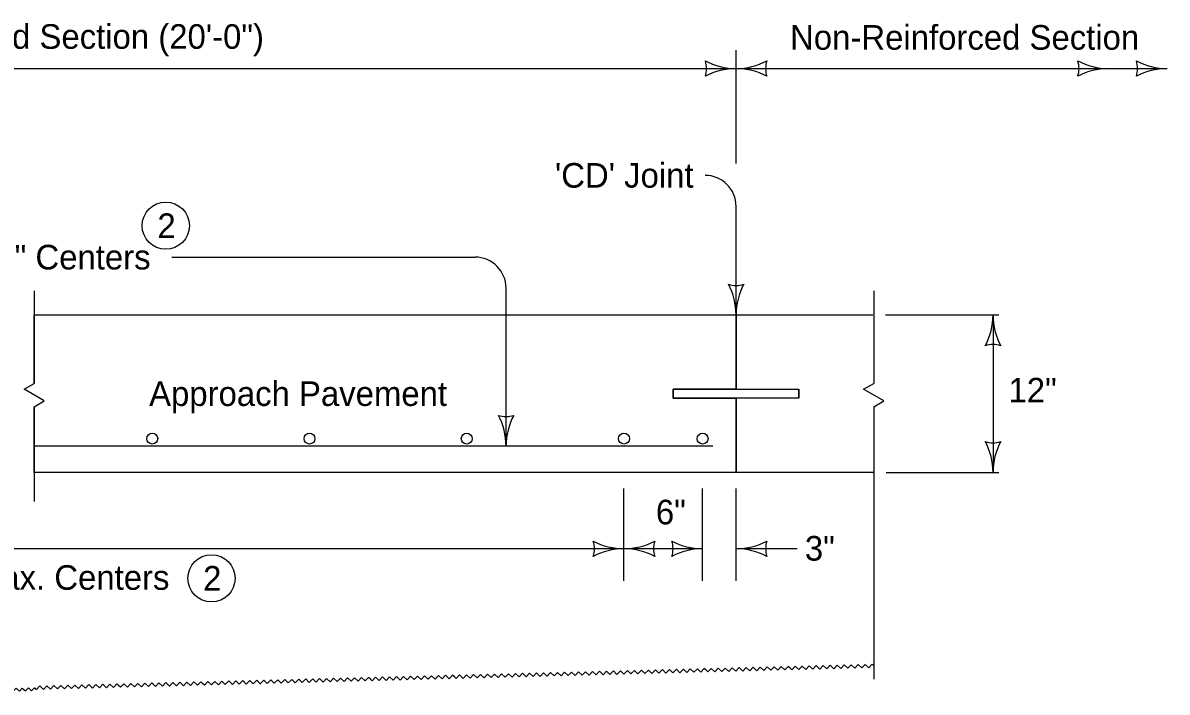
# Model space of a CAD drawing. Extents: x -2134860 to -2124557, y -2139046 to -2137324.
# Drawn here: x -2132638 to -2131894, y -2137759 to -2137324 of the extents above; entities that cross this region are included whole.
import ezdxf

# ---------------------------------------------------------------- set-up
doc = ezdxf.new("R2010")
doc.units = 0
for name, color, linetype in [('BridgeSuperStructureExisting', 7, 'Continuous'), ('dsnCellElements', 7, 'Continuous'), ('dsnStdLabel', 7, 'Continuous')]:
    doc.layers.add(name, color=color, linetype=linetype)

msp = doc.modelspace()

# ---------------------------------------------------------------- linework, layer by layer
at = {"layer": 'BridgeSuperStructureExisting'}
for p, q in [((-2132630.71, -2137498.29), (-2132630.71, -2137558.37)), ((-2132084.45, -2137498.29), (-2132084.45, -2137558.37)), ((-2132173.99, -2137562.24), (-2132173.99, -2137513.93)), ((-2132214.91, -2137567.92), (-2132214.91, -2137562.24)), ((-2132214.91, -2137562.24), (-2132133.06, -2137562.24)), ((-2132133.06, -2137562.24), (-2132133.06, -2137567.92)), ((-2132133.06, -2137567.92), (-2132214.91, -2137567.92)), ((-2132173.99, -2137616.23), (-2132173.99, -2137567.92)), ((-2132630.71, -2137573.53), (-2132630.71, -2137635.08)), ((-2132084.45, -2137573.53), (-2132084.45, -2137750.77)), ((-2132189.05, -2137599.18), (-2132630.71, -2137599.18))]:
    msp.add_line(p, q, dxfattribs=at)
for points in [[(-2132630.7, -2137573.53), (-2132624.14, -2137569.74), (-2132637.28, -2137562.15), (-2132630.7, -2137558.37)], [(-2132084.45, -2137573.53), (-2132077.88, -2137569.74), (-2132091.01, -2137562.15), (-2132084.45, -2137558.37)]]:
    msp.add_lwpolyline(points, dxfattribs=at)
for centre, radius in [((-2132545.06, -2137455.88), 15.36), ((-2132553.84, -2137594.28), 3.55), ((-2132451.53, -2137594.28), 3.55), ((-2132349.23, -2137594.28), 3.55), ((-2132246.92, -2137594.28), 3.55), ((-2132195.77, -2137594.28), 3.55), ((-2132515.3, -2137685.11), 15.36)]:
    msp.add_circle(centre, radius, dxfattribs=at)
for centre, radius, start, end in [((-2132049.33, -2137513.93), 42.5, 331.92751, 360), ((-2132049.33, -2137513.93), 42.5, 331.92751, 360), ((-2131964.33, -2137513.93), 42.5, 180, 208.07249), ((-2131964.33, -2137513.93), 42.5, 180, 208.07249), ((-2132006.83, -2137549.56), 16.42, 72.26665, 107.73335), ((-2132006.83, -2137549.56), 16.42, 72.26665, 107.73335), ((-2132006.83, -2137580.59), 16.42, 252.26665, 287.73335), ((-2132049.33, -2137616.23), 42.5, 360, 28.07249), ((-2131964.33, -2137616.23), 42.5, 151.92751, 180)]:
    msp.add_arc(centre, radius, start, end, dxfattribs=at)
at = {"layer": 'dsnCellElements'}
for centre, radius, start, end in [((-2132209.62, -2137353.72), 16.42, 342.26665, 17.73335), ((-2132173.99, -2137311.22), 42.5, 241.92751, 270), ((-2132173.99, -2137396.22), 42.5, 90, 118.07249), ((-2132173.99, -2137311.22), 42.5, 270, 298.07249), ((-2132173.99, -2137396.22), 42.5, 61.92751, 90), ((-2132138.35, -2137353.72), 16.42, 162.26665, 197.73335), ((-2131967.29, -2137353.72), 16.42, 342.26665, 17.73335), ((-2131931.65, -2137311.22), 42.5, 241.92751, 270), ((-2131931.65, -2137396.22), 42.5, 90, 118.07249), ((-2131929.18, -2137353.72), 16.42, 342.26665, 17.73335), ((-2131893.54, -2137311.22), 42.5, 241.92751, 270), ((-2131893.54, -2137396.22), 42.5, 90, 118.07249), ((-2132173.99, -2137478.29), 16.42, 252.26665, 287.73335), ((-2132216.49, -2137513.92), 42.5, 360, 28.07249), ((-2132131.49, -2137513.92), 42.5, 151.92751, 180), ((-2132323.65, -2137563.54), 16.42, 252.26665, 287.73335), ((-2132366.15, -2137599.18), 42.5, 360, 28.07249), ((-2132281.15, -2137599.18), 42.5, 151.92751, 180), ((-2132282.56, -2137665.9), 16.42, 342.26665, 17.73335), ((-2132246.92, -2137623.4), 42.5, 241.92751, 270), ((-2132246.92, -2137708.4), 42.5, 90, 118.07249), ((-2132246.92, -2137623.4), 42.5, 270, 298.07249), ((-2132246.92, -2137708.4), 42.5, 61.92751, 90), ((-2132211.29, -2137665.9), 16.42, 162.26665, 197.73335), ((-2132231.41, -2137665.9), 16.42, 342.26665, 17.73335), ((-2132195.77, -2137623.4), 42.5, 241.92751, 270), ((-2132195.77, -2137708.4), 42.5, 90, 118.07249), ((-2132173.99, -2137623.4), 42.5, 270, 298.07249), ((-2132173.99, -2137708.4), 42.5, 61.92751, 90), ((-2132138.35, -2137665.9), 16.42, 162.26665, 197.73335)]:
    msp.add_arc(centre, radius, start, end, dxfattribs=at)
at = {"layer": 'dsnStdLabel'}
for p, q in [((-2132173.99, -2137415.38), (-2132173.99, -2137341.67)), ((-2133142.62, -2137353.72), (-2132173.99, -2137353.72)), ((-2132173.99, -2137353.72), (-2131893.54, -2137353.72)), ((-2132173.99, -2137513.92), (-2132173.99, -2137443.35)), ((-2132541.02, -2137476.32), (-2132343.86, -2137476.32)), ((-2132323.65, -2137599.18), (-2132323.65, -2137496.53)), ((-2132630.71, -2137558.37), (-2132630.71, -2137513.92)), ((-2132630.71, -2137513.92), (-2132173.99, -2137513.92)), ((-2132630.71, -2137513.92), (-2132173.99, -2137513.92)), ((-2132173.99, -2137513.92), (-2132173.99, -2137562.24)), ((-2132173.99, -2137513.93), (-2132084.95, -2137513.93)), ((-2132076.84, -2137513.93), (-2132003.01, -2137513.93)), ((-2132006.83, -2137513.93), (-2132006.83, -2137616.23)), ((-2132630.7, -2137558.37), (-2132630.71, -2137558.37)), ((-2132173.99, -2137562.24), (-2132214.91, -2137562.24)), ((-2132214.91, -2137562.24), (-2132214.91, -2137567.92)), ((-2132214.91, -2137562.24), (-2132214.91, -2137567.92)), ((-2132133.06, -2137567.92), (-2132133.06, -2137562.24)), ((-2132214.91, -2137567.92), (-2132173.99, -2137567.92)), ((-2132173.99, -2137567.92), (-2132173.99, -2137616.23)), ((-2132173.99, -2137616.23), (-2132173.99, -2137567.92)), ((-2132630.71, -2137616.23), (-2132630.71, -2137573.53)), ((-2132173.99, -2137616.23), (-2132630.71, -2137616.23)), ((-2132173.99, -2137616.23), (-2132630.71, -2137616.23)), ((-2132084.45, -2137616.23), (-2132173.99, -2137616.23)), ((-2132076.34, -2137616.23), (-2132003.01, -2137616.23)), ((-2132246.92, -2137686.69), (-2132246.92, -2137626.72)), ((-2132195.77, -2137686.69), (-2132195.77, -2137626.72)), ((-2132173.99, -2137686.69), (-2132173.99, -2137626.72)), ((-2132246.92, -2137665.9), (-2133069.68, -2137665.9)), ((-2132195.77, -2137665.9), (-2132246.92, -2137665.9)), ((-2132134.21, -2137665.9), (-2132173.99, -2137665.9))]:
    msp.add_line(p, q, dxfattribs=at)
for points in [[(-2132630.7, -2137573.53), (-2132624.14, -2137569.74), (-2132637.28, -2137562.15), (-2132630.7, -2137558.37)], [(-2132084.27, -2137742.05), (-2132085.44, -2137740.95), (-2132087.65, -2137743.28), (-2132089.99, -2137741.06), (-2132092.21, -2137743.4), (-2132094.54, -2137741.18), (-2132096.75, -2137743.51), (-2132099.09, -2137741.3), (-2132101.3, -2137743.63), (-2132103.64, -2137741.42), (-2132105.85, -2137743.76), (-2132108.19, -2137741.54), (-2132110.4, -2137743.87), (-2132112.74, -2137741.66), (-2132114.96, -2137743.99), (-2132117.29, -2137741.77), (-2132119.51, -2137744.11), (-2132121.84, -2137741.9), (-2132124.06, -2137744.23), (-2132126.39, -2137742.01), (-2132128.61, -2137744.34), (-2132130.94, -2137742.13), (-2132133.16, -2137744.47), (-2132135.5, -2137742.25), (-2132137.71, -2137744.58), (-2132138.88, -2137743.48)], [(-2132411.91, -2137750.61), (-2132413.08, -2137749.5), (-2132415.3, -2137751.83), (-2132417.63, -2137749.62), (-2132419.85, -2137751.95), (-2132422.18, -2137749.74), (-2132424.4, -2137752.07), (-2132426.73, -2137749.86), (-2132428.94, -2137752.19), (-2132431.29, -2137749.98), (-2132433.5, -2137752.31), (-2132435.83, -2137750.1), (-2132438.05, -2137752.43), (-2132440.38, -2137750.21), (-2132442.6, -2137752.55), (-2132444.94, -2137750.33), (-2132447.15, -2137752.67), (-2132449.48, -2137750.46), (-2132451.7, -2137752.78), (-2132454.03, -2137750.57), (-2132456.25, -2137752.9), (-2132458.59, -2137750.69), (-2132460.8, -2137753.02), (-2132463.14, -2137750.81), (-2132465.35, -2137753.14), (-2132466.52, -2137752.03)], [(-2132357.3, -2137749.18), (-2132358.47, -2137748.07), (-2132360.69, -2137750.41), (-2132363.02, -2137748.19), (-2132365.24, -2137750.53), (-2132367.57, -2137748.31), (-2132369.79, -2137750.64), (-2132372.13, -2137748.43), (-2132374.34, -2137750.76), (-2132376.68, -2137748.55), (-2132378.89, -2137750.88), (-2132381.22, -2137748.67), (-2132383.44, -2137751), (-2132385.78, -2137748.79), (-2132387.99, -2137751.12), (-2132390.32, -2137748.91), (-2132392.54, -2137751.24), (-2132394.88, -2137749.03), (-2132397.1, -2137751.36), (-2132399.43, -2137749.15), (-2132401.65, -2137751.48), (-2132403.98, -2137749.26), (-2132406.19, -2137751.6), (-2132408.53, -2137749.38), (-2132410.74, -2137751.72), (-2132411.91, -2137750.61)], [(-2132302.7, -2137747.76), (-2132303.86, -2137746.65), (-2132306.08, -2137748.98), (-2132308.42, -2137746.77), (-2132310.63, -2137749.1), (-2132312.96, -2137746.89), (-2132315.18, -2137749.22), (-2132317.52, -2137747), (-2132319.73, -2137749.34), (-2132322.07, -2137747.12), (-2132324.29, -2137749.45), (-2132326.62, -2137747.24), (-2132328.84, -2137749.58), (-2132331.17, -2137747.36), (-2132333.39, -2137749.7), (-2132335.72, -2137747.48), (-2132337.93, -2137749.81), (-2132340.27, -2137747.6), (-2132342.49, -2137749.93), (-2132344.82, -2137747.72), (-2132347.04, -2137750.05), (-2132349.37, -2137747.84), (-2132351.59, -2137750.17), (-2132353.92, -2137747.96), (-2132356.14, -2137750.29), (-2132357.3, -2137749.18)], [(-2132248.09, -2137746.33), (-2132249.26, -2137745.22), (-2132251.48, -2137747.55), (-2132253.81, -2137745.34), (-2132256.03, -2137747.67), (-2132258.36, -2137745.46), (-2132260.57, -2137747.79), (-2132262.91, -2137745.58), (-2132265.13, -2137747.91), (-2132267.46, -2137745.7), (-2132269.68, -2137748.03), (-2132272.02, -2137745.82), (-2132274.23, -2137748.15), (-2132276.57, -2137745.94), (-2132278.78, -2137748.27), (-2132281.11, -2137746.06), (-2132283.33, -2137748.39), (-2132285.66, -2137746.17), (-2132287.88, -2137748.51), (-2132290.21, -2137746.29), (-2132292.43, -2137748.62), (-2132294.76, -2137746.41), (-2132296.98, -2137748.74), (-2132299.32, -2137746.53), (-2132301.53, -2137748.86), (-2132302.7, -2137747.76)], [(-2132193.48, -2137744.9), (-2132194.65, -2137743.79), (-2132196.86, -2137746.13), (-2132199.2, -2137743.92), (-2132201.41, -2137746.24), (-2132203.76, -2137744.03), (-2132205.97, -2137746.37), (-2132208.3, -2137744.15), (-2132210.52, -2137746.49), (-2132212.86, -2137744.27), (-2132215.07, -2137746.6), (-2132217.4, -2137744.39), (-2132219.62, -2137746.72), (-2132221.95, -2137744.51), (-2132224.17, -2137746.84), (-2132226.51, -2137744.63), (-2132228.72, -2137746.96), (-2132231.06, -2137744.75), (-2132233.27, -2137747.08), (-2132235.61, -2137744.87), (-2132237.82, -2137747.2), (-2132240.16, -2137744.98), (-2132242.37, -2137747.32), (-2132244.71, -2137745.1), (-2132246.92, -2137747.43), (-2132248.09, -2137746.33)], [(-2132138.88, -2137743.48), (-2132140.04, -2137742.37), (-2132142.26, -2137744.7), (-2132144.59, -2137742.49), (-2132146.81, -2137744.82), (-2132149.15, -2137742.61), (-2132151.36, -2137744.94), (-2132153.7, -2137742.73), (-2132155.91, -2137745.06), (-2132158.25, -2137742.85), (-2132160.46, -2137745.18), (-2132162.79, -2137742.96), (-2132165.01, -2137745.3), (-2132167.35, -2137743.08), (-2132169.57, -2137745.42), (-2132171.9, -2137743.21), (-2132174.11, -2137745.53), (-2132176.45, -2137743.32), (-2132178.66, -2137745.65), (-2132181, -2137743.44), (-2132183.22, -2137745.78), (-2132185.55, -2137743.56), (-2132187.77, -2137745.89), (-2132190.1, -2137743.68), (-2132192.32, -2137746.01), (-2132193.48, -2137744.9)], [(-2132667.05, -2137758.08), (-2132666.18, -2137757.17), (-2132664.15, -2137759.1), (-2132662.21, -2137757.06), (-2132660.18, -2137758.99), (-2132658.24, -2137756.96), (-2132656.21, -2137758.89), (-2132654.28, -2137756.86), (-2132652.24, -2137758.78), (-2132650.31, -2137756.75), (-2132648.27, -2137758.68), (-2132646.34, -2137756.65), (-2132644.31, -2137758.58), (-2132642.38, -2137756.55), (-2132640.34, -2137758.47), (-2132638.41, -2137756.44), (-2132636.37, -2137758.37), (-2132634.44, -2137756.34), (-2132632.41, -2137758.27), (-2132630.47, -2137756.23), (-2132629.46, -2137757.2)], [(-2132575.73, -2137754.88), (-2132576.9, -2137753.78), (-2132579.12, -2137756.11), (-2132581.45, -2137753.9), (-2132583.67, -2137756.23), (-2132586, -2137754.02), (-2132588.22, -2137756.35), (-2132590.55, -2137754.13), (-2132592.77, -2137756.47), (-2132595.11, -2137754.25), (-2132597.32, -2137756.59), (-2132599.65, -2137754.38), (-2132601.87, -2137756.7), (-2132604.21, -2137754.49), (-2132606.42, -2137756.82), (-2132608.76, -2137754.61), (-2132610.97, -2137756.94), (-2132613.31, -2137754.73), (-2132615.52, -2137757.06), (-2132617.86, -2137754.85), (-2132620.08, -2137757.18), (-2132622.41, -2137754.97), (-2132624.63, -2137757.3), (-2132626.96, -2137755.09), (-2132629.18, -2137757.42), (-2132630.34, -2137756.32)], [(-2132521.13, -2137753.46), (-2132522.29, -2137752.35), (-2132524.51, -2137754.68), (-2132526.85, -2137752.47), (-2132529.06, -2137754.8), (-2132531.4, -2137752.59), (-2132533.61, -2137754.93), (-2132535.94, -2137752.71), (-2132538.17, -2137755.04), (-2132540.49, -2137752.83), (-2132542.71, -2137755.16), (-2132545.04, -2137752.94), (-2132547.27, -2137755.28), (-2132549.6, -2137753.07), (-2132551.82, -2137755.4), (-2132554.15, -2137753.18), (-2132556.36, -2137755.52), (-2132558.7, -2137753.3), (-2132560.92, -2137755.64), (-2132563.25, -2137753.42), (-2132565.47, -2137755.76), (-2132567.8, -2137753.54), (-2132570.01, -2137755.87), (-2132572.35, -2137753.66), (-2132574.57, -2137755.99), (-2132575.73, -2137754.88)], [(-2132466.52, -2137752.03), (-2132467.69, -2137750.92), (-2132469.9, -2137753.26), (-2132472.24, -2137751.05), (-2132474.45, -2137753.38), (-2132476.79, -2137751.17), (-2132479, -2137753.49), (-2132481.34, -2137751.28), (-2132483.56, -2137753.62), (-2132485.89, -2137751.4), (-2132488.11, -2137753.74), (-2132490.44, -2137751.52), (-2132492.66, -2137753.85), (-2132494.99, -2137751.64), (-2132497.21, -2137753.97), (-2132499.54, -2137751.76), (-2132501.75, -2137754.09), (-2132504.09, -2137751.88), (-2132506.31, -2137754.21), (-2132508.65, -2137752), (-2132510.86, -2137754.33), (-2132513.19, -2137752.12), (-2132515.41, -2137754.45), (-2132517.74, -2137752.23), (-2132519.96, -2137754.57), (-2132521.13, -2137753.46)]]:
    msp.add_lwpolyline(points, dxfattribs=at)
for centre in [(-2132194.2, -2137443.35), (-2132343.86, -2137496.53)]:
    msp.add_arc(centre, 20.21, 0, 90, dxfattribs=at)

# ---------------------------------------------------------------- texts
for s, p in [('Single Reinforced Section (20\'-0")', (-2132802.07, -2137340.88)), ('Non-Reinforced Section', (-2132138.86, -2137341.46)), ("'CD' Joint", (-2132291.84, -2137431.14)), ('2', (-2132550.49, -2137463.88)), ('#5 Bars At 12" Centers', (-2132773.04, -2137484.32)), ('12"', (-2131996.75, -2137570.81)), ('Approach Pavement', (-2132555.91, -2137573.07)), ('6"', (-2132226.18, -2137650.05)), ('3"', (-2132129.24, -2137673.61)), ('#5 Bars At 12" max. Centers', (-2132813.08, -2137692.58)), ('2', (-2132520.74, -2137693.11))]:
    msp.add_text(s, height=16, dxfattribs=at).set_placement(p)

doc.saveas('drawing.dxf')
